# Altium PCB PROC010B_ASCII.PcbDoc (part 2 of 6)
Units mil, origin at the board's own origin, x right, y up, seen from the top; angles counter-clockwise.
Board outline 3180 x 2565 mil, 6 copper layers (TOP, L2, L3, L4, L5, BOTTOM), stack 55.54 mil thick; 362 components, 264 nets, 1248 pads, 1144 vias.
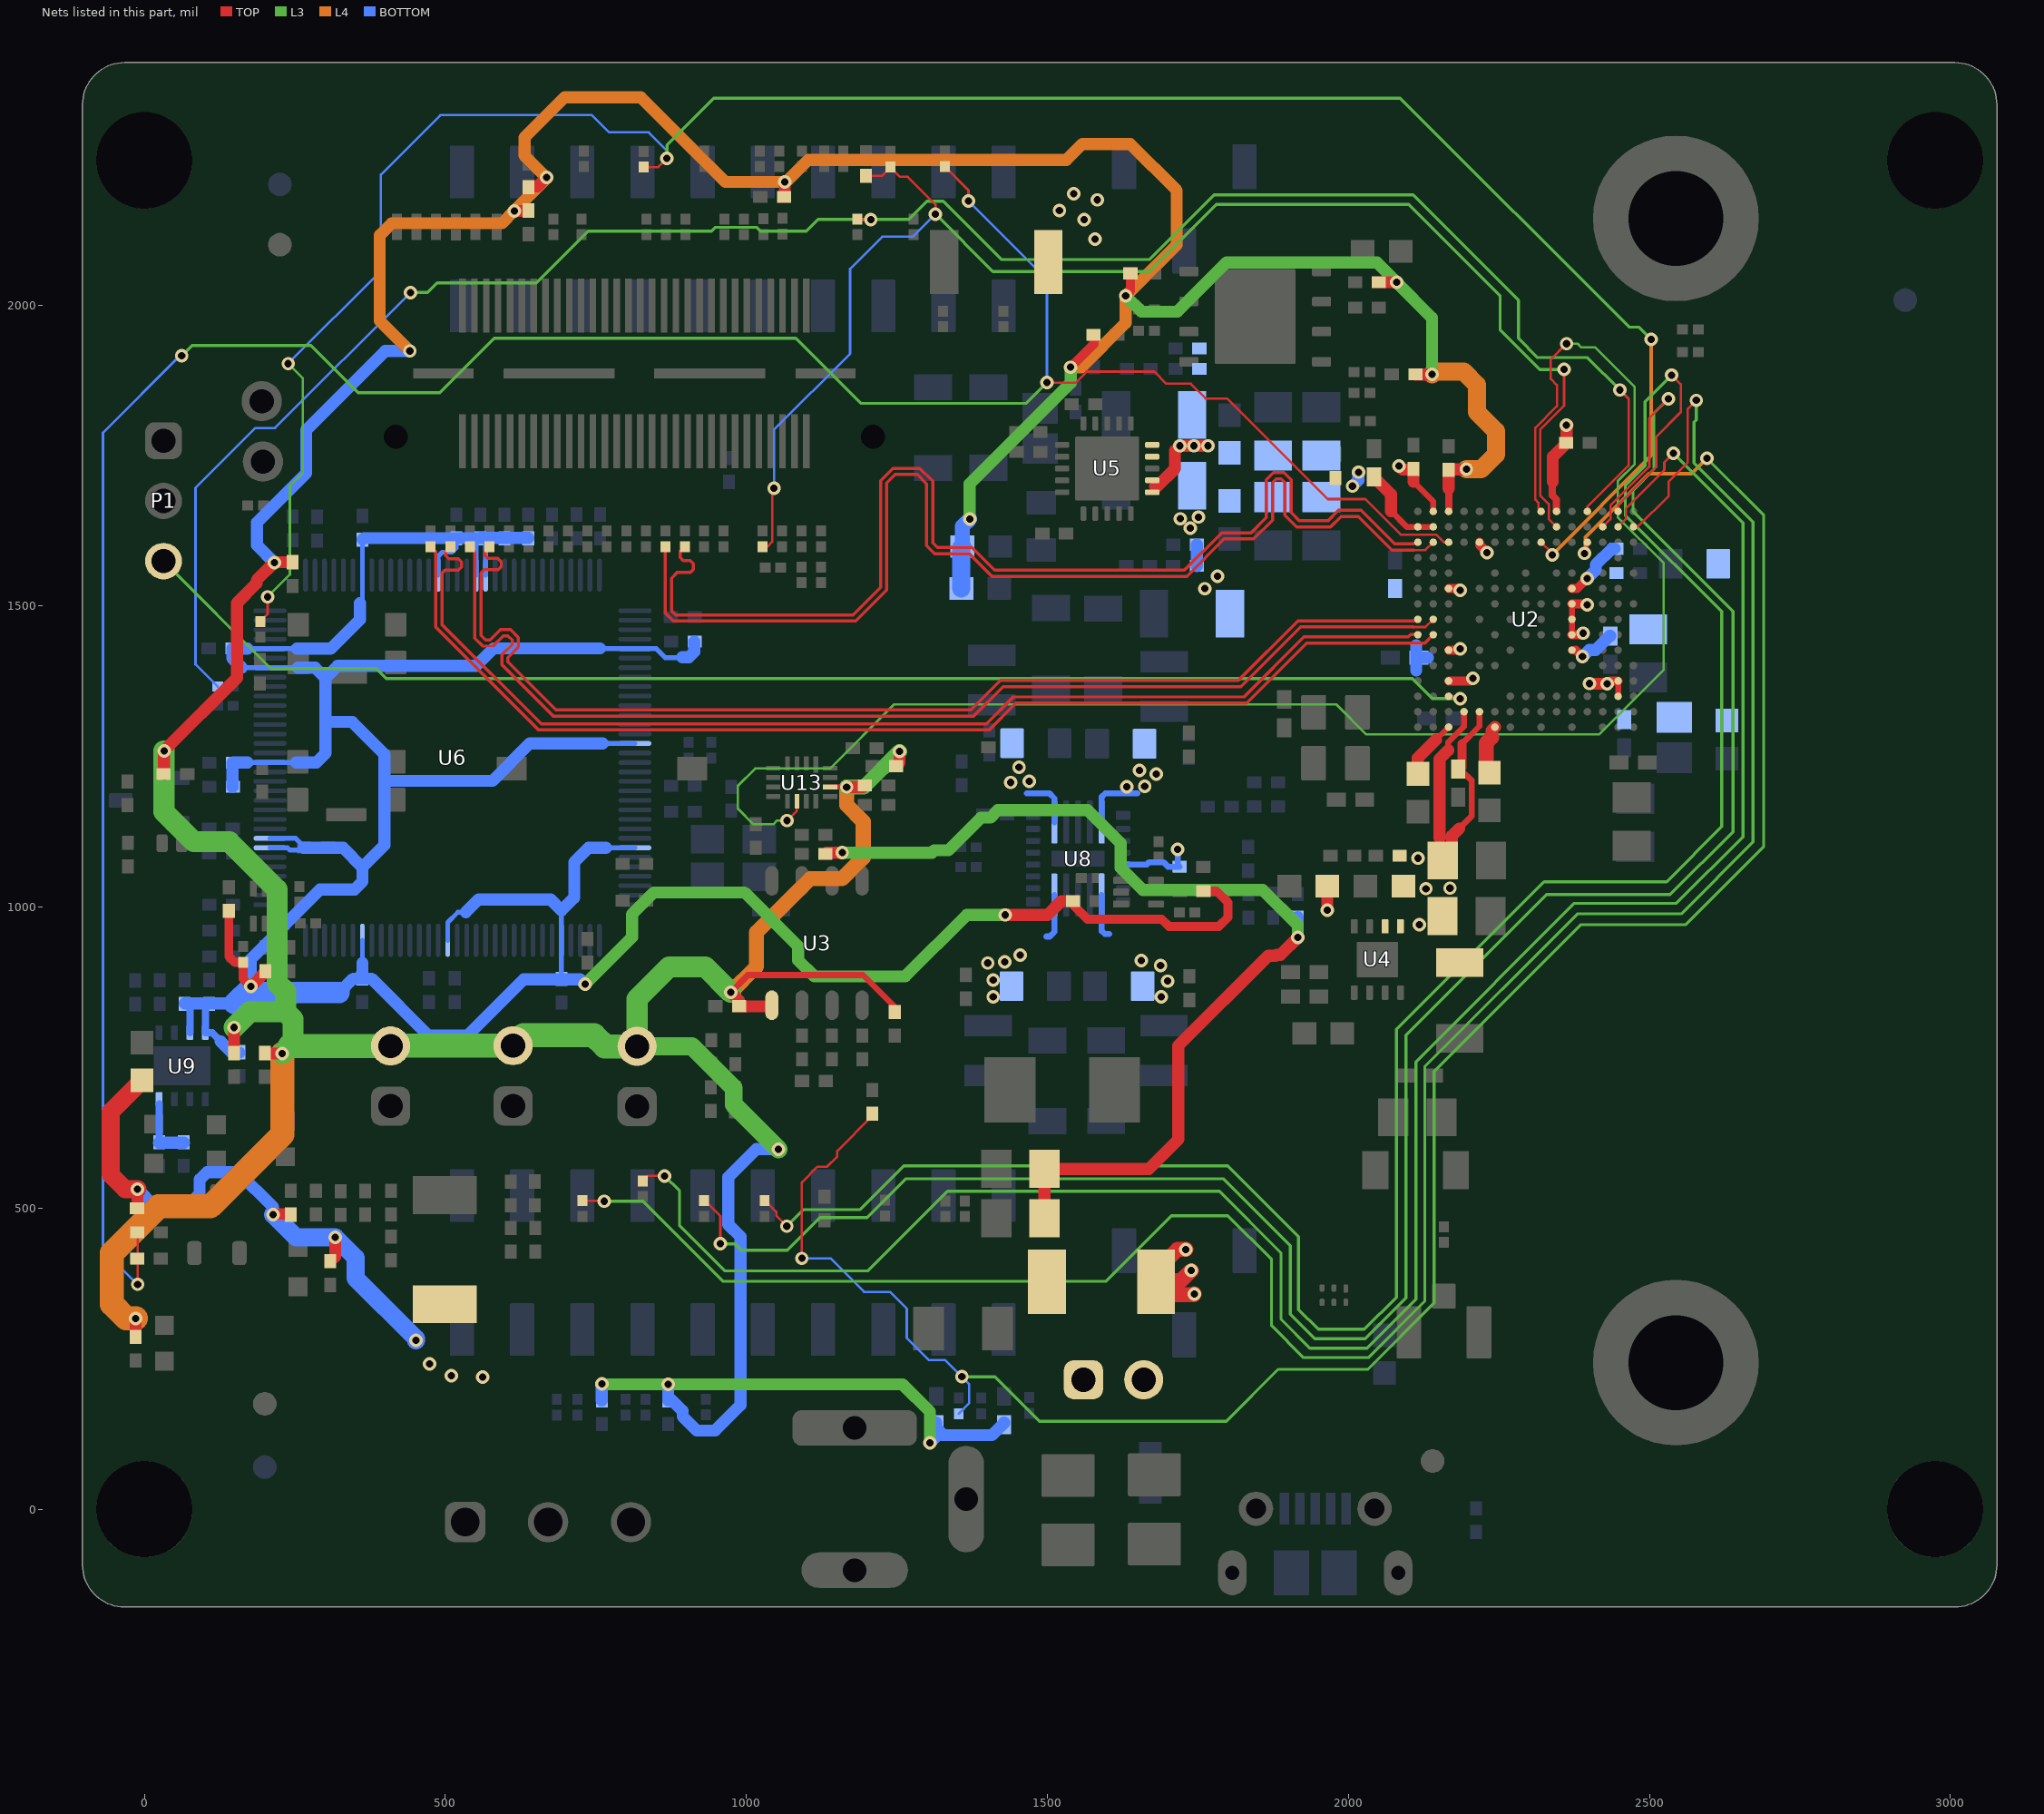
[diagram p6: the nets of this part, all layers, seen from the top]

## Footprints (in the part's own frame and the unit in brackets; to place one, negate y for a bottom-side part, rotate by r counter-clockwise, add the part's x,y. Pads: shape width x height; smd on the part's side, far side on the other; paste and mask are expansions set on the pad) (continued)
ABL0161A [mm] "BGA, 161-Balls, Body 10.4x10.4mm, Pitch 0.65mm"
  round 0.32 smd mask+0: A1(-4.55,4.55) A2(-3.9,4.55) A3(-3.25,4.55) A5(-1.95,4.55) A7(-0.65,4.55) A9(0.65,4.55) A10(1.3,4.55) A13(3.25,4.55) A14(3.9,4.55) A15(4.55,4.55) B1(-4.55,3.9) B2(-3.9,3.9) B3(-3.25,3.9) B4(-2.6,3.9) B5(-1.95,3.9) B6(-1.3,3.9) B7(-0.65,3.9) B8(0,3.9) B9(0.65,3.9) B10(1.3,3.9) B11(1.95,3.9) B12(2.6,3.9) B13(3.25,3.9) B14(3.9,3.9) B15(4.55,3.9) C1(-4.55,3.25) C2(-3.9,3.25) C3(-3.25,3.25) C4(-2.6,3.25) C5(-1.95,3.25) C6(-1.3,3.25) C7(-0.65,3.25) C8(0,3.25) C9(0.65,3.25) C13(3.25,3.25) C14(3.9,3.25) C15(4.55,3.25) D1(-4.55,2.6) D2(-3.9,2.6) D13(3.25,2.6) D15(4.55,2.6) E1(-4.55,1.95) E2(-3.9,1.95) E3(-3.25,1.95) E5(-1.95,1.95) E6(-1.3,1.95) E8(0,1.95) E10(1.3,1.95) E11(1.95,1.95) E13(3.25,1.95) E14(3.9,1.95) E15(4.55,1.95) F2(-3.9,1.3) F3(-3.25,1.3) F5(-1.95,1.3) F9(0.65,1.3) F11(1.95,1.3) F13(3.25,1.3) F14(3.9,1.3) G1(-4.55,0.65) G2(-3.9,0.65) G3(-3.25,0.65) G5(-1.95,0.65) G6(-1.3,0.65) G7(-0.65,0.65) G8(0,0.65) G10(1.3,0.65) G13(3.25,0.65) G14(3.9,0.65) G15(4.55,0.65) H2(-3.9,0) H3(-3.25,0) H5(-1.95,0) H7(-0.65,0) H9(0.65,0) H11(1.95,0) H13(3.25,0) H14(3.9,0) H15(4.55,0) J1(-4.55,-0.65) J2(-3.9,-0.65) J3(-3.25,-0.65) J5(-1.95,-0.65) J6(-1.3,-0.65) J7(-0.65,-0.65) J8(0,-0.65) J10(1.3,-0.65) J13(3.25,-0.65) J14(3.9,-0.65) J15(4.55,-0.65) K2(-3.9,-1.3) K3(-3.25,-1.3) K5(-1.95,-1.3) K7(-0.65,-1.3) K8(0,-1.3) K9(0.65,-1.3) K10(1.3,-1.3) K11(1.95,-1.3) K13(3.25,-1.3) K14(3.9,-1.3) K15(4.55,-1.3) L1(-4.55,-1.95) L2(-3.9,-1.95) L3(-3.25,-1.95) L5(-1.95,-1.95) L6(-1.3,-1.95) L8(0,-1.95) L10(1.3,-1.95) L13(3.25,-1.95) L14(3.9,-1.95) L15(4.55,-1.95) M2(-3.9,-2.6) M3(-3.25,-2.6) M13(3.25,-2.6) M14(3.9,-2.6) M15(4.55,-2.6) N1(-4.55,-3.25) N2(-3.9,-3.25) N3(-3.25,-3.25) N4(-2.6,-3.25) N5(-1.95,-3.25) N6(-1.3,-3.25) N7(-0.65,-3.25) N8(0,-3.25) N9(0.65,-3.25) N10(1.3,-3.25) N11(1.95,-3.25) N12(2.6,-3.25) N13(3.25,-3.25) N14(3.9,-3.25) N15(4.55,-3.25) P1(-4.55,-3.9) P2(-3.9,-3.9) P3(-3.25,-3.9) P4(-2.6,-3.9) P5(-1.95,-3.9) P6(-1.3,-3.9) P7(-0.65,-3.9) P8(0,-3.9) P9(0.65,-3.9) P10(1.3,-3.9) P11(1.95,-3.9) P12(2.6,-3.9) P13(3.25,-3.9) P14(3.9,-3.9) P15(4.55,-3.9) R1(-4.55,-4.55) R2(-3.9,-4.55) R3(-3.25,-4.55) R4(-2.6,-4.55) R5(-1.95,-4.55) R6(-1.3,-4.55) R7(-0.65,-4.55) R8(0,-4.55) R9(0.65,-4.55) R10(1.3,-4.55) R11(1.95,-4.55) R12(2.6,-4.55) R13(3.25,-4.55) R14(3.9,-4.55) R15(4.55,-4.55)
  silkscreen extent -5.3,-5.3 5.3,5.3
AssemblyNote [mil] "Assembly Note"
AssemblyNoteLabel [mil] "Assembly Note for PCB Labels"
CE_Mark_5mm [mil] "Minimum text height for CE Mark"
CONN_105017-0001 [mm] "Molex Micro USB-B"
  rect 0.4x1.35 smd: 1(-1.3,1.35) 2(-0.65,1.35) 3(0,1.35) 4(0.65,1.35) 5(1.3,1.35)
  oval 1.2x1.9 hole 0.6 slot 1.3 at 90 deg: 6(-3.5,-1.35) 9(3.5,-1.35)
  rect 1.5x1.9 smd: 7(-1,-1.35) 8(1,-1.35)
  round 1.45 hole 0.85: 10(2.5,1.35) 11(-2.5,1.35)
  TOP region: 3.5,-2.3 2.3,-2.3 2.3,-0.4 3.5,-0.4
  TOP region: -3.5,-0.4 -2.3,-0.4 -2.3,-2.3 -3.5,-2.3
  silkscreen extent -4.1,-0.2 4.1,1.4
CUI_PJ-002AH [mm] "DC POWER JACK, R/A, TH"
  rrect50% 1.5x5.25 hole 1 slot 3.5 at 90 deg: 1(-3,0)
  oval 1.5x4.5 hole 1 slot 3 at 90 deg: 2(3,0)
  oval 4.5x1.5 hole 1 slot 3 at 0 deg: 3(0,4.7)
  silkscreen extent -4.1,-4.5 10.7,4.5
D0008A_L [mm] "SOIC, 8-Leads, Body 4.9x3.9mm, Pitch 1.27mm, IPC High Density"
  oval 1.25x0.55 smd: 1(-2.625,1.905) 2(-2.625,0.635) 3(-2.625,-0.635) 4(-2.625,-1.905) 5(2.625,-1.905) 6(2.625,-0.635) 7(2.625,0.635) 8(2.625,1.905)
  silkscreen extent -3.1,-2.5 0.9,2.5
DBZ0003A_N [mm] "SOT23, 3-Leads, Body 2.9x1.3mm, Pitch 0.95mm, Lead Span 2.4mm, IPC Medium Density"
  rrect17% 1x0.6 smd: 1(-1.2,0.95) 2(-1.2,-0.95) 3(1.2,0)
  silkscreen extent 0.2,-1.5 0.7,1.5
DFE252012P [mm] "TOKO, Pad sizes increased as per request"
  rect 0.9x2 smd: 1(-1.05,0) 2(1.05,0)
  silkscreen extent -0.3,-1.2 0.3,1.2
DRB0008A [mm] "SON, 8-Leads, Body 3x3mm, Pitch 0.65mm, Thermal Pad 1.75x1.5mm, TI Recommended"
  rrect33% 0.6x0.3 smd: 1(-1.4,0.975) 2(-1.4,0.325) 3(-1.4,-0.325) 4(-1.4,-0.975) 5(1.4,-0.975) 6(1.4,-0.325) 7(1.4,0.325) 8(1.4,0.975)
  rrect7% 1.5x1.75 smd paste-0.75: 9(0,0)
  silkscreen extent -1.73,-1.73 1.73,1.73
DRB0008B [mm] "SON, 8-Leads, Body 3x3mm, Pitch 0.65mm, Thermal Pad 2.4x1.65mm, TI Recommended"
  rrect33% 0.6x0.3 smd: 1(-1.4,0.975) 2(-1.4,0.325) 3(-1.4,-0.325) 4(-1.4,-0.975) 5(1.4,-0.975) 6(1.4,-0.325) 7(1.4,0.325) 8(1.4,0.975)
  rrect9% 1.47x1.06 on Bottom Paste: 9(0,-0.63) 9(0,0.63)
  rrect6% 1.65x2.4 smd paste-1.2: 9(0,0)
  silkscreen extent -1.73,-1.73 1.73,1.73
DRL0006A [mm] "SOTFL, 6-Flat Leads, Body 1.2x1.6x0.6mm, Pitch 0.5mm, TI recommended"
  rrect33% 0.67x0.3 smd: 1(-0.74,0.5) 2(-0.74,0) 3(-0.74,-0.5) 4(0.74,-0.5) 5(0.74,0) 6(0.74,0.5)
  silkscreen extent -0.9,-0.95 0.5,0.95
DRY0006A [mm] "PSON, 6-Leads, Body 1x1.45mm, Pitch 0.5mm, TI Recommended"
  rrect50% 0.35x0.2 smd: 1(-0.275,0.5)
  rrect50% 0.3x0.2 smd: 2(-0.3,0) 3(-0.3,-0.5) 4(0.3,-0.5) 5(0.3,0) 6(0.3,0.5)
ESD_Overlay_Small [mil]
  silkscreen extent -62,-48 64,61
FCC_disclaimer [mil]
Fiducial10-20 [mm]
  round 1 smd mask+0: 1(0,0)
  TOP keep-out circle w1.178: c0,0 r0.5
IEC_HotSurface_Small [mil]
  silkscreen extent -107,-93 107,92
Johnson_128-0711-201 [mm] "UMC Straight Jack Receptacle, 50 Ohm, SMT"
  rrect10% 1x1.05 smd: 1(0,1.525)
  rrect10% 1.05x2.2 smd: 2(-1.475,0) 3(1.475,0)
  silkscreen extent -0.6,-1.3 0.6,-1.3
Kyocera_CX3225SA [mm] "SMD, 4-Leads, Body 3.2x2.5mm"
  rrect10% 1.05x1.45 smd: 1(-0.925,1.075) 2(-0.925,-1.075) 3(0.925,-1.075) 4(0.925,1.075)
  silkscreen extent -1.86,1.09 -1.74,1.21
Label_650x200 [mil] "Thermal Transfer Label"
  round 1 on Mech13: 0(0,0)
  silkscreen extent -325,-100 325,100
NDK_NX3225SA [mm] "NDK"
  rect 1.2x1.4 smd: 1(-0.8,1.1) 2(-0.8,-1.1) 3(0.8,-1.1) 4(0.8,1.1)
NLCV32 [mm] "TDK"
  rect 1.2x2 smd: 1(-1.6,0) 2(1.6,0)
  silkscreen extent -0.9,-1.4 0.9,1.4
On-Shore_OSTTE030161 [mm] "Terminal Block, 3.5mm, 3x1, TH"
  rrect50% 1.7x1.7 hole 1.2: 1(-3.5,0)
  round 1.7 hole 1.2: 2(0,0) 3(3.5,0)
  silkscreen extent -5.25,-3.6 5.25,4.05
PDT0128A [mm] "Thin QFP, 128-Leads, Body 14x14mm, Pitch 0.4mm"
  oval 1.4x0.2 smd: 1(-7.7,6.2) 2(-7.7,5.8) 3(-7.7,5.4) 4(-7.7,5) 5(-7.7,4.6) 6(-7.7,4.2) 7(-7.7,3.8) 8(-7.7,3.4) 9(-7.7,3) 10(-7.7,2.6) 11(-7.7,2.2) 12(-7.7,1.8) 13(-7.7,1.4) 14(-7.7,1) 15(-7.7,0.6) 16(-7.7,0.2) 17(-7.7,-0.2) 18(-7.7,-0.6) 19(-7.7,-1) 20(-7.7,-1.4) 21(-7.7,-1.8) 22(-7.7,-2.2) 23(-7.7,-2.6) 24(-7.7,-3) 25(-7.7,-3.4) 26(-7.7,-3.8) 27(-7.7,-4.2) 28(-7.7,-4.6) 29(-7.7,-5) 30(-7.7,-5.4) 31(-7.7,-5.8) 32(-7.7,-6.2) 65(7.7,-6.2) 66(7.7,-5.8) 67(7.7,-5.4) 68(7.7,-5) 69(7.7,-4.6) 70(7.7,-4.2) 71(7.7,-3.8) 72(7.7,-3.4) 73(7.7,-3) 74(7.7,-2.6) 75(7.7,-2.2) 76(7.7,-1.8) 77(7.7,-1.4) 78(7.7,-1) 79(7.7,-0.6) 80(7.7,-0.2) 81(7.7,0.2) 82(7.7,0.6) 83(7.7,1) 84(7.7,1.4) 85(7.7,1.8) 86(7.7,2.2) 87(7.7,2.6) 88(7.7,3) 89(7.7,3.4) 90(7.7,3.8) 91(7.7,4.2) 92(7.7,4.6) 93(7.7,5) 94(7.7,5.4) 95(7.7,5.8) 96(7.7,6.2)
  oval 0.2x1.4 smd: 33(-6.2,-7.7) 34(-5.8,-7.7) 35(-5.4,-7.7) 36(-5,-7.7) 37(-4.6,-7.7) 38(-4.2,-7.7) 39(-3.8,-7.7) 40(-3.4,-7.7) 41(-3,-7.7) 42(-2.6,-7.7) 43(-2.2,-7.7) 44(-1.8,-7.7) 45(-1.4,-7.7) 46(-1,-7.7) 47(-0.6,-7.7) 48(-0.2,-7.7) 49(0.2,-7.7) 50(0.6,-7.7) 51(1,-7.7) 52(1.4,-7.7) 53(1.8,-7.7) 54(2.2,-7.7) 55(2.6,-7.7) 56(3,-7.7) 57(3.4,-7.7) 58(3.8,-7.7) 59(4.2,-7.7) 60(4.6,-7.7) 61(5,-7.7) 62(5.4,-7.7) 63(5.8,-7.7) 64(6.2,-7.7) 97(6.2,7.7) 98(5.8,7.7) 99(5.4,7.7) 100(5,7.7) 101(4.6,7.7) 102(4.2,7.7) 103(3.8,7.7) 104(3.4,7.7) 105(3,7.7) 106(2.6,7.7) 107(2.2,7.7) 108(1.8,7.7) 109(1.4,7.7) 110(1,7.7) 111(0.6,7.7) 112(0.2,7.7) 113(-0.2,7.7) 114(-0.6,7.7) 115(-1,7.7) 116(-1.4,7.7) 117(-1.8,7.7) 118(-2.2,7.7) 119(-2.6,7.7) 120(-3,7.7) 121(-3.4,7.7) 122(-3.8,7.7) 123(-4.2,7.7) 124(-4.6,7.7) 125(-5,7.7) 126(-5.4,7.7) 127(-5.8,7.7) 128(-6.2,7.7)
  silkscreen extent -7.7,-6.3 6.3,6.99
RNF0026C [mm] "QFN, 26-Leads, Body 4x4.5mm, Pitch 0.5mm"
  rrect25% 0.6x0.4 smd paste-0.3: 1(-1.9,1.825) 8(-1.9,-1.825) 14(1.9,-1.825) 21(1.9,1.825)
  rrect40% 0.6x0.25 smd paste+0: 2(-1.9,1.25) 3(-1.9,0.75) 4(-1.9,0.25) 5(-1.9,-0.25) 6(-1.9,-0.75) 7(-1.9,-1.25) 15(1.9,-1.25) 16(1.9,-0.75) 17(1.9,-0.25) 18(1.9,0.25) 19(1.9,0.75) 20(1.9,1.25)
  rrect40% 0.25x1.82 smd paste-1: 9(-1,-1.54) 10(-0.5,-1.54) 11(0,-1.54) 12(0.5,-1.54) 13(1,-1.54) 22(1,1.54) 23(0.5,1.54) 24(0,1.54) 25(-0.5,1.54) 26(-1,1.54)
  rrect15% 2.24x0.66 smd paste-1: 27(0,0)
  rrect33% 0.6x0.3 on Bottom Paste: ""(-1.9,-1.775) ""(-1.9,1.775) ""(1.9,-1.775) ""(1.9,1.775)
  rrect33% 0.3x0.825 on Bottom Paste: ""(-1.575,-2.037) ""(-1.575,2.037) ""(1.575,-2.037) ""(1.575,2.037)
  rrect40% 0.25x0.81 on Bottom Paste: ""(-1,-2.045) ""(-1,-1.035) ""(-1,1.035) ""(-1,2.045) ""(-0.5,-2.045) ""(-0.5,-1.035) ""(-0.5,1.035) ""(-0.5,2.045) ""(0,-2.045) ""(0,-1.035) ""(0,1.035) ""(0,2.045) ""(0.5,-2.045) ""(0.5,-1.035) ""(0.5,1.035) ""(0.5,2.045) ""(1,-2.045) ""(1,-1.035) ""(1,1.035) ""(1,2.045)
  rrect15% 0.98x0.66 on Bottom Paste: ""(-0.59,0) ""(0.59,0)
  silkscreen extent -2.45,-2.7 2.45,2.7
RSV0016A [mm] "QFN, 16-Leads, Body 1.8x2.6mm, Pitch 0.4mm, TI Recommended"
  rect 0.7x0.2 smd: 1(-0.75,0.6)
  rect 0.6x0.2 smd: 2(-0.8,0.2) 3(-0.8,-0.2) 4(-0.8,-0.6) 9(0.8,-0.6) 10(0.8,-0.2) 11(0.8,0.2) 12(0.8,0.6)
  rect 0.2x0.6 smd: 5(-0.6,-1.2) 6(-0.2,-1.2) 7(0.2,-1.2) 8(0.6,-1.2) 13(0.6,1.2) 14(0.2,1.2) 15(-0.2,1.2) 16(-0.6,1.2)
  silkscreen extent -1.08,-1.33 1.08,1.45
RTJ0020D [mm] "QFN, 20-Leads, Body 4x4mm, Pitch 0.5mm, Thermal Pad 2.7x2.7mm, TI Recommended"
  rrect42% 0.6x0.24 smd: 1(-1.9,1) 2(-1.9,0.5) 3(-1.9,0) 4(-1.9,-0.5) 5(-1.9,-1) 11(1.9,-1) 12(1.9,-0.5) 13(1.9,0) 14(1.9,0.5) 15(1.9,1)
  rrect42% 0.24x0.6 smd: 6(-1,-1.9) 7(-0.5,-1.9) 8(0,-1.9) 9(0.5,-1.9) 10(1,-1.9) 16(1,1.9) 17(0.5,1.9) 18(0,1.9) 19(-0.5,1.9) 20(-1,1.9)
  rrect8% 1.19x1.19 on Top Paste: 21(-0.695,-0.695) 21(-0.695,0.695) 21(0.695,-0.695) 21(0.695,0.695)
  rrect4% 2.7x2.7 smd paste-1.4: 21(0,0)
  silkscreen extent -2.22,-2.22 2.23,2.23
Samtec_QSH-030-01-X-D-A [mm] "Receptacle, 0.5 mm, 30x2, TH"
  rect 2.27x0.279 smd: 1(-2.865,7.25) 2(2.865,7.25) 3(-2.865,6.75) 4(2.865,6.75) 5(-2.865,6.25) 6(2.865,6.25) 7(-2.865,5.75) 8(2.865,5.75) 9(-2.865,5.25) 10(2.865,5.25) 11(-2.865,4.75) 12(2.865,4.75) 13(-2.865,4.25) 14(2.865,4.25) 15(-2.865,3.75) 16(2.865,3.75) 17(-2.865,3.25) 18(2.865,3.25) 19(-2.865,2.75) 20(2.865,2.75) 21(-2.865,2.25) 22(2.865,2.25) 23(-2.865,1.75) 24(2.865,1.75) 25(-2.865,1.25) 26(2.865,1.25) 27(-2.865,0.75) 28(2.865,0.75) 29(-2.865,0.25) 30(2.865,0.25) 31(-2.865,-0.25) 32(2.865,-0.25) 33(-2.865,-0.75) 34(2.865,-0.75) 35(-2.865,-1.25) 36(2.865,-1.25) 37(-2.865,-1.75) 38(2.865,-1.75) 39(-2.865,-2.25) 40(2.865,-2.25) 41(-2.865,-2.75) 42(2.865,-2.75) 43(-2.865,-3.25) 44(2.865,-3.25) 45(-2.865,-3.75) 46(2.865,-3.75) 47(-2.865,-4.25) 48(2.865,-4.25) 49(-2.865,-4.75) 50(2.865,-4.75) 51(-2.865,-5.25) 52(2.865,-5.25) 53(-2.865,-5.75) 54(2.865,-5.75) 55(-2.865,-6.25) 56(2.865,-6.25) 57(-2.865,-6.75) 58(2.865,-6.75) 59(-2.865,-7.25) 60(2.865,-7.25)
  round 0 hole 1.02 unplated mask+0: MH1(2.67,10.065) MH2(2.67,-10.065)
  rect 0.43x2.54 smd: MP1(0,8.065) MP4(0,-8.065)
  rect 0.43x4.7 smd: MP2(0,3.175) MP3(0,-3.175)
  silkscreen extent -3.9,-10.66 3.62,10.66
Samtec_SSM-103-x-SV [mm] "Receptacle, 2.54mm, 3x1, SMT"
  rrect10% 1.02x1.905 smd: 1(-2.54,-1.777) 2(0,1.777) 3(2.54,-1.777)
  silkscreen extent -3.81,-2.27 3.81,1.28
Samtec_SSM-110-x-DV [mm] "Receptacle, 2.54mm, 10x2, SMT"
  rrect10% 1.02x2.22 smd: 1(-11.43,2.825) 2(-11.43,-2.825) 3(-8.89,2.825) 4(-8.89,-2.825) 5(-6.35,2.825) 6(-6.35,-2.825) 7(-3.81,2.825) 8(-3.81,-2.825) 9(-1.27,2.825) 10(-1.27,-2.825) 11(1.27,2.825) 12(1.27,-2.825) 13(3.81,2.825) 14(3.81,-2.825) 15(6.35,2.825) 16(6.35,-2.825) 17(8.89,2.825) 18(8.89,-2.825) 19(11.43,2.825) 20(11.43,-2.825)
  silkscreen extent -13.02,-2.54 12.7,2.54
Samtec_TSW-101-17-T-S [mm] "Samtec,CONN HEADER 1POS .100\" SNGL TIN"
  round 1.7 hole 1.02: 1(0,0)
  silkscreen extent -1.27,-1.27 1.27,1.27
Samtec_TSW-103-07-T-S [mm] "Header, 2.54 mm, 3x1, TH"
  rrect50% 1.55x1.55 hole 1.02: 1(-2.54,0)
  round 1.55 hole 1.02: 2(0,0) 3(2.54,0)
SMB [mil] "Molded Diode, 2-Leads, Body 5.4x3.6mm, IPC Medium Density, based on OnSemi component dimensions"
  rect 85x107.99 smd: 1(-87.01,0) 2(87.01,0)
  silkscreen extent -155,-82 125,82
SML-E1_Yellow [mm] "SMD, 2-Leads, Body 1.6x0.8mm"
  rect 0.8x0.8 smd: 1(0.825,0) 2(-0.825,0)
  silkscreen extent -1.8,-0.8 1.3,0.8
SML-LX0603SRW_SuperRed [mm] "Lumex Opto/Components Inc"
  rect 0.8x0.8 smd: 1(-0.75,0) 2(0.75,0)
  silkscreen extent 1.4,-0.53 1.78,0.53
SOD-882 [mm] "Skyworks"
  rrect42% 0.475x0.75 smd: 1(-0.412,0) 2(0.412,0)
  silkscreen extent -1.1,-0.35 -0.87,0.35
SOT-23 [mm] "SOT23, 3-Leads, Body 2.9x1.3mm, Pitch 0.95mm, Lead Span 2.5mm, IPC Medium Density"
  rrect50% 1x0.6 smd: 1(-1.2,0.95) 2(-1.2,-0.95) 3(1.2,0)
  silkscreen extent -1.62,-1.5 0.7,1.5
SW_CHS-01TB [mm] "CHS Recommended footprint"
  rect 1x1.27 smd: 1(0,3.81) 2(0,-3.81)
  silkscreen extent -1.3,-4.05 1.3,4.05
SW_KMR243GLFG [mm] "SMD, 5-Leads, Body 4.2x2.8mm"
  rrect11% 0.9x1 smd: 1(-2.05,0.8) 2(2.05,0.8) 3(-2.05,-0.8) 4(2.05,-0.8)
  rrect18% 1.7x0.55 smd: 5(0,1.425)
  silkscreen extent -3.1,0.7 -2.9,0.9
TI_Stacked_Overlay_Small [mil]
TSW-102-07-G-S [mm] "Samtec 100mil, 1x2, 230 mil above insulator"
  rrect50% 1.65x1.65 hole 1.016: 1(-1.27,0)
  round 1.65 hole 1.016: 2(1.27,0)
WEEE_Minimum [mil] "WEEElie bin"
  silkscreen extent 22,-71 54,74
WSON-8L_6x5MM_EP [mm] "SMD, 8-Leads, Body 6x5mm, Pitch 1.27mm"
  rrect25% 0.8x0.4 smd: 1(-2.8,1.905) 2(-2.8,0.635) 3(-2.8,-0.635) 4(-2.8,-1.905) 5(2.8,-1.905) 6(2.8,-0.635) 7(2.8,0.635) 8(2.8,1.905)
  rrect3% 3.4x4 smd paste-3: 9(0,0)
  rrect7% 1.468x1.698 on Top Paste: ""(-0.834,-0.949) ""(-0.834,0.949) ""(0.834,-0.949) ""(0.834,0.949)
  silkscreen extent -3.2,-2.7 3.2,2.7

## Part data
C1 C13 C14 C33 C36 C91: library part CMP-0007136-5, "CAP, CERM, 1 uF, 16 V, +/- 10%, X7R, AEC-Q200 Grade 1, 0603"
C2 C21: library part CMP-0006325-2, "CAP, CERM, 0.1 uF, 50 V, +/- 10%, X7R, AEC-Q200 Grade 1, 0402"
C3 C5 C7 C10 C12 C39 C47 C48 C51 C53 C56 C57 C68: library part CMP-0078265-1, "CAP, CERM, 0.22 µF, 16 V,+/- 10%, X7R, AEC-Q200 Grade 1, 0402"
C4 C6 C11: library part CMP-0006351-2, "CAP, CERM, 0.1 uF, 16 V, +/- 10%, X7R, 0402"
C8: library part CMP-0078219-1, "CAP, CERM, 0.1 µF, 10 V,+/- 10%, X7S, 0201"
C9 C15: library part CMP-0006367-2, "CAP, CERM, 4.7 pF, 50 V, +/- 2%, C0G/NP0, 0402"
C16 C20 C42 C43 C49 C64 C67 C71 C75 C76 C79 C84 C85 C90: library part CMP-0078241-1, "CAP, CERM, 0.1 µF, 10 V,+/- 10%, X7R, 0402"
C17 C19 C23 C32 C34 C35 C37 C38 C40 C45 C52 C58 C59 C60 C65 C72 C73 C83: library part CMP-0008017-2, "CAP, CERM, 10 uF, 10 V, +/- 10%, X7R, 0805"
C18 C22: library part CMP-0007138-4, "CAP, CERM, 0.47 uF, 16 V, +/- 10%, X7R, AEC-Q200 Grade 1, 0603"
C24: library part CMP-0078221-1, "CAP, CERM, 4700 pF, 50 V,+/- 10%, X7R, 0402"
C25 C30 C31: library part CMP-0008770-2, "CAP, CERM, 22 uF, 6.3 V, +/- 10%, X7R, AEC-Q200 Grade 1, 1206"
C26 C27: library part CMP-0078216-1, "CAP, TA, 47 µF, 10 V, +/- 10%, SMD"
C28 C29 C44 C46: library part CMP-0078224-1, "CAP, CERM, 0.01 µF, 50 V,+/- 10%, X8R, AEC-Q200 Grade 0, 0402"
C41 C61 C62: library part CMP-0078222-1, "CAP, CERM, 1 µF, 6.3 V,+/- 20%, X7S, 0402"
C50: library part CMP-0078220-1, "CAP, CERM, 0.01 µF, 25 V,+/- 10%, X7R, 0402"
C54 C55 C81 C82: library part CMP-0008811-2, "CAP, CERM, 22 uF, 10 V, +/- 10%, X7R, AEC-Q200 Grade 1, 1206"
C63 C70: library part CMP-0006494-2, "CAP, CERM, 8 pF, 50 V, +/- 6%, C0G/NP0, 0402"
C66 C69: library part CMP-0078218-1, "CAP, CERM, 0.01 µF, 16 V,+/- 10%, X7R, 0402"
C74 C77 C80: library part CMP-0006302-2, "CAP, CERM, 2.2 uF, 10 V, +/- 10%, X7S, 0402"
C78: library part CMP-0078217-1, "CAP, CERM, 15 pF, 50 V,+/- 1%, C0G/NP0, 0402"
C86 C87 C88 C89: library part CMP-0078223-1, "CAP, CERM, 390 pF, 50 V,+/- 5%, C0G/NP0, AEC-Q200 Grade 0, 0402"
"CAUTION HOT SURFACE1": library part CMP-0074837-1, "IEC 61010-1 Hot Surface Warning"
D2: library part CMP-0078187-1, "Diode, Schottky,  V, 0.01 A, SOD-882"
D3: library part CMP-0078243-1, "Diode, TVS, Uni, 5.8 V, 10.5 Vc, AEC-Q101, SMB"
DS1 DS2 DS5: library part CMP-0002876-1, "LED, Super Red, SMD"
DS3 DS4: library part CMP-0002977-2, "LED, Yellow, SMD"
"ESD Susceptible1": library part CMP-0074840-1, "ESD Susceptible Symbol"
F1: library part CMP-0003458-2, "Fuse, 5 A, 32VAC/VDC, SMD"
FB1 FB2: library part CMP-0003364-1, "Ferrite Bead, 30 ohm @ 100 MHz, 4 A, 0805"
FID1 FID2 FID3 FID4 FID5 FID6 FID7: library part CMP-0077181-1, "Fiducial mark.  There is nothing to buy or mount."
J1: library part CMP-0075524-1, "Receptacle, 0.5 mm, 30x2, Gold, TH"
J2: library part CMP-0055788-1, "UMC Straight Jack Receptacle, 50 Ohm, Gold, SMT"
J3: library part CMP-0075352-1, "Terminal Block, 3.5mm, 3x1, Tin, R/A, TH"
J4 J7: library part CMP-0078183-1, "Receptacle, 2.54mm, 3x1, Gold with Tin tail, SMT"
J5 J6: library part CMP-0078182-1, "Receptacle, 2.54mm, 10x2, Gold with Tin tail, SMT"
J8: library part CMP-0055293-1, "Connector, Receptacle, Micro-USB Type B, R/A, Bottom Mount SMT"
L1 L2 L3 L4: library part CMP-0058946-1, "Inductor, Shielded, 470 nH, 4.7 A, 0.021 ohm, SMD"
L5 L7 L8 L9: library part CMP-0083745-1, "Inductor, Wirewound, Ferrite, 100 nH, 2.85 A, 0.024 ohm, AEC-Q200 Grade 1, SMD"
LBL1: library part CMP-0003625-1, "Thermal Transfer Printable Labels, 0.650\" W x 0.200\" H - 10,000 per roll"
Logo1: library part CMP-0074838-1, "Texas Instrument Corporate Signature"
Logo2: library part CMP-0074847-1, "FCC_disclaimer"
Logo3: library part CMP-0074769-1
LOGO4: library part CMP-0074844-1
P1: library part CMP-0075530-2, "Header, 2.54 mm, 3x1, Tin, TH"
P2 P3 P4 P5: library part CMP-0075405-2, "Header, 100mil, 2x1, Gold, TH"
P6: library part CMP-0078270-1, "DC POWER JACK, R/A, TH"
Q1 Q2: library part CMP-0000947-2, "MOSFET, N-CH, 100 V, 0.17 A, SOT-23"
R1 R2 R3 R4 R5 R6 R7 R8 R9 R10 R17 R18 R19 R20 R21 R22 R23 R24 R25 R26 R27 R28 R29 R30 R31 R32 R33 R35 R36 R48 R49 R50 R51 R52 R53 R54 R55 R56 R57 R58 R59 R60 R61 R62 R63 R64 R65 R66 R67 R69 R70 R71 R72 R75 R76 R94 R102 R104 R105 R106 R108 R109 R111 R135 R136 R144 R146 R162 R163 R164 R165 R166 R167 R168 R169 R180 R181 R182 R185 R186 R188 R197 R198: library part CMP-0027008-4, "RES, 0, 5%, 0.05 W, 0201"
R11 R12 R37 R78 R97 R107 R119 R120 R128 R129 R141 R152 R159 R177 R183 R187: library part CMP-0026992-2, "RES, 0, 5%, 0.063 W, 0402"
R13 R14 R15 R16 R41 R43 R46 R47 R73 R74 R81 R83 R84 R86 R89 R91 R98 R113 R145 R148 R155 R178 R179 R184 R196: library part CMP-0025958-3, "RES, 10.0 k, 1%, 0.063 W, AEC-Q200 Grade 0, 0402"
R34 R115 R118: library part CMP-0016044-3, "RES, 0, 5%, 0.75 W, AEC-Q200 Grade 0, 2010"
R38: library part CMP-0026395-2, "RES, 47.5 k, 1%, 0.063 W, AEC-Q200 Grade 0, 0402"
R39 R40 R42 R44 R45: library part CMP-0027275-3, "RES, 33.2, 1%, 0.05 W, 0201"
R68 R77 R79 R80 R154: library part CMP-0026993-2, "RES, 100, 5%, 0.1 W, AEC-Q200 Grade 0, 0402"
R82: library part CMP-0025993-3, "RES, 12.7 k, 1%, 0.063 W, AEC-Q200 Grade 0, 0402"
R85 R87: library part CMP-0026491-2, "RES, 61.9, 1%, 0.063 W, AEC-Q200 Grade 0, 0402"
R88 R96 R114: library part CMP-0026574-2, "RES, 82.5 k, 1%, 0.063 W, AEC-Q200 Grade 0, 0402"
R90 R189: library part CMP-0078194-1, "RES, 360, 5%, 0.1 W, AEC-Q200 Grade 0, 0402"
R92 R95 R99: library part CMP-0026557-2, "RES, 7.87 k, 1%, 0.063 W, AEC-Q200 Grade 0, 0402"
R93 R101 R112: library part CMP-0026542-2, "RES, 750, 1%, 0.063 W, AEC-Q200 Grade 0, 0402"
R100 R103 R116 R117 R160: library part CMP-0078212-1, "RES, 510, 5%, 0.1 W, AEC-Q200 Grade 0, 0402"
R110 R138 R158 R172 R173: library part CMP-0025950-3, "RES, 100 k, 1%, 0.063 W, AEC-Q200 Grade 0, 0402"
R121 R132: library part CMP-0078211-2, "RES, 3.00 k, 1%, 0.063 W, AEC-Q200 Grade 0, 0402"
R122 R131 R139: library part CMP-0026099-2, "RES, 1.96 k, 1%, 0.063 W, AEC-Q200 Grade 0, 0402"
R123 R124 R126 R127 R140: library part CMP-0026071-3, "RES, 1.00 k, 1%, 0.063 W, AEC-Q200 Grade 0, 0402"
R125 R195: library part CMP-0025958-2, "RES, 10.0 k, 1%, 0.063 W, 0402"
R130 R133 R137 R161 R175 R176: library part CMP-0025884-3, "RES, 0, 5%, 0.125 W, 0603"
R134: library part CMP-0026404-2, "RES, 49.9, 1%, 0.063 W, AEC-Q200 Grade 0, 0402"
R142 R150: library part CMP-0026701-1, "RES, 4.99 k, 1%, 0.1 W, AEC-Q200 Grade 0, 0402"
R143 R147: library part CMP-0026414-2, "RES, 4.99 k, 1%, 0.063 W, AEC-Q200 Grade 0, 0402"
R149: library part CMP-0078193-1, "RES, 1.0 k, 5%, 0.1 W, AEC-Q200 Grade 0, 0402"
R151 R153: library part CMP-0078210-2, "RES, 330 k, 1%, 0.063 W, AEC-Q200 Grade 0, 0402"
R156: library part CMP-0026403-2, "RES, 49.9 k, 1%, 0.063 W, AEC-Q200 Grade 0, 0402"
R157 R174: library part CMP-0078244-2, "RES, 30.0 k, 1%, 0.063 W, AEC-Q200 Grade 0, 0402"
R170 R171: library part CMP-0026244-2, "RES, 2.94 k, 1%, 0.063 W, AEC-Q200 Grade 0, 0402"
R190 R191 R192 R193: library part CMP-0026363-2, "RES, 3.83, 1%, 0.063 W, AEC-Q200 Grade 0, 0402"
R194: library part CMP-0026413-2, "RES, 4.87 k, 1%, 0.063 W, AEC-Q200 Grade 0, 0402"
S1: library part CMP-0002163-2, "Switch, Slide, SPST, Top Slide, SMT"
SW1 SW2: library part CMP-0002325-1, "Switch, SPST-NO, Off-Mom, 0.01 A, 32 VDC, SMD"
TP1 TP2: library part CMP-0055993-1, "Header, 100mil, 1x1, Tin, TH"
U1: library part CMP-0079267-1, "2.3V-3.6V, 16M-BIT [x 1/x 2/x 4] CMOS FLASH Memory, WSON-8"
U2: library part CMP-0081285-1, "Single Chip 77 and 79 GHz FMCW Transceiver, ABL0161A (FCBGA-161)"
U3: library part CMP-0075992-1, "Automotive Fault Protected CAN Transceiver With Flexible Data-Rate, D0008A (SOIC-8)"
U4: library part CMP-0073870-2, "Automotive Low-Noise, Wide-Bandwidth, High PSRR, Low-Dropout 1-A Linear Regulator, DRB0008A (VSON-8)"
U5: library part CMP-0073732-2, "Dual, 1-A, Low Noise (3.8-uVRMS), LDO Voltage Regulator, RTJ0020D (WQFN-20)"
U6: library part CMP-0029856-2, "Tiva C Series Microcontroller, 1024 KB Flash, 256 KB SRAM, 12 Bit, 20 Channels, -40 to 105 degC, 128-Pin TQFP (PDT), Green (RoHS & no Sb/Br), Tray"
U7: library part CMP-0033001-1, "Precision Micropower Shunt Voltage Reference, 0.5% accuracy, 2.5 V, 15 ppm / degC, 15 mA, -40 to 125 degC, 3-pin SOT-23 (DBZ), Green (RoHS & no Sb/Br)"
U8: library part CMP-0079120-1, "4-A + 2.5-A + Two 1.5-A Buck Converters With Integrated Switches, RNF0026C (VQFN-HR-26)"
U9: library part CMP-0036402-3, "Single Output High PSRR LDO, 1 A, Adjustable 1.2 to 5.5 V Output, 2.7 to 5.5 V Input, 8-pin SON (DRB), -40 to 125 degC, Green (RoHS & no Sb/Br)"
U10: library part CMP-0043115-2, "ESD-Protection Array for High-Speed Data Interfaces, 4 Channels, -40 to +85 degC, 6-pin SON (DRY), Green (RoHS & no Sb/Br)"
U11 U12: library part CMP-0067397-2, "1.4V-Capable +/-0.5degC Temperature Sensor with Alert Function and I2C/SMBus interface in SOT-563, DRL0006A (SOT-OTHER-6)"
U13: library part CMP-0067415-1, "10-Ohm Quad SPDT Analog Switch, RSV0016A (UQFN-16)"
Y1: library part CMP-0004694-3, "Crystal, 40 MHz, 8pF, SMD"
Y2: library part CMP-0078214-2, "Crystal, 16 MHz, 15 ppm, 8 pF, AEC-Q200 Grade 1, SMD"
ZZ1: library part CMP-0003616-3
ZZ2: library part CMP-0077236-1
ZZ3: library part CMP-0077237-1
ZZ4: library part CMP-0077238-1
ZZ5: library part CMP-0077238-1, "Micro USB cable, Brackets, Screws, Nuts, Jumpers and Bump on need to be placed in a platic bag"

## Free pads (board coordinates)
  round 275.59 hole 157.48: 0(2543.95,2143.55) 1(2543.95,243.55)
  round 160 hole 160 unplated: ""(0,0) ""(0,2240) ""(2974.5,0) ""(2974.5,2240)

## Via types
v1: diameter 22.4, hole 12.2, TOP to BOTTOM, tented both sides, 621 vias
v2: diameter 15.74, hole 5.9, TOP to L2, tented top, 508 vias
v3: diameter 19.68, hole 7.87, TOP to BOTTOM, tented top, 7 vias
v4: diameter 19.68, hole 7.87, TOP to BOTTOM, 4 vias
v5: diameter 19.68, hole 7.87, TOP to BOTTOM, tented both sides, 3 vias
v6: diameter 19.68, hole 7.87, TOP to BOTTOM, tented bottom, 1 vias

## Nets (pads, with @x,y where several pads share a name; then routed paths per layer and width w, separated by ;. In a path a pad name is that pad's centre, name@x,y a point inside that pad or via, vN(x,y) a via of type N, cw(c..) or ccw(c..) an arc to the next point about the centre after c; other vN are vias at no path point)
3V3_BRD: C41.2 C42.2 C43.2 C50.2 C61.2 C76.2 C77.2 C78.2 R124.2 R127.2 R134.2 R140.2 R155.2 R156.2 R179.2 R183.2 R184.2 R187.2 R188.1 U6.7 U6.8 U6.16 U6.26 U6.28 U6.39 U6.47 U6.51 U6.52 U6.69 U6.79 U6.90 U6.101 U6.113 U6.122 U9.3 U9.4 | length 6461.6
  TOP w15: R184.2@140.38,994.45 R184.2@140.38,993.66 140.38,918.01 150.16,908.23 R188.1@163.83,908.23 163.83,881.17 v1(177,868) ; R179.2@1543.45,1009.92 1543.45,1003.19 1566.64,980 1690,980 1702,968 1784.72,968 1799.73,983.01 1799.73,1007.95 1781,1026.68 R183.2@1759.34,1026.68 R183.2@1758.55,1026.68
  TOP w20: v1(177,868) 200.98,891.98 R187.2@200.98,893.66 ; v1(1430,987) 1500.36,987 1523.28,1009.92 R179.2@1542.66,1009.92 R179.2@1543.45,1009.92
  L3 w20: v1(732,872) 810.21,950.21 810.21,988.21 846.3,1024.3 996.79,1024.3 1086.18,934.9 1086.18,911.5 1112.78,884.9 1263.9,884.9 1366,987 v1(1430,987)
  BOTTOM w8: 161.85,1397.65 254.85,1397.65 ; 171.33,1240.17 252.33,1240.17 ; 171.36,1429.14 253.36,1429.14 ; U6.7@208.64,1098.43 238.07,1098.43 242,1094.5 260.32,1094.5 264.25,1098.43 264.25,1101.25 251.32,1114.18 U6.8@208.64,1114.18 ; 362.18,907.32 U6.122@362.18,944.89 ; 362.18,1508.68 C43.2@362.18,1610.21 ; U6.47@488.17,1551.19 488.17,1582.5 495.15,1589.48 511.07,1589.48 518.22,1596.62 C42.2@518.22,1612.16 ; U6.113@503.92,944.89 503.92,974.56 520.86,991.5 534,991.5 ; C42.2@518.03,1612.36 C42.2@518.22,1612.55 ; U6.51@551.16,1551.19 551.16,1605.41 558.3,1612.55 566.91,1603.94 U6.52@566.91,1551.19 ; R155.2@692.89,880.16 692.89,994.61 ; 757,1429.5 757.36,1429.14 850.37,1429.14 865.11,1414.4 892.75,1414.4 ; 761.16,1271.66 U6.79@814.94,1271.66 ; 767,1098.5 814.87,1098.5 U6.90@814.94,1098.43
  BOTTOM w8.4: 358,1504.5 362.18,1508.68 ; C43.2@362.18,1610.21 C43.2@362.52,1610.55 ; R155.2@692.78,880.05 R155.2@692.89,880.16 ; 892.75,1414.4 893.34,1414.99
  BOTTOM w12: C78.2@67.1,839.85 75.63,831.32 U9.3@75.63,791.44 ; C77.2@108.82,839.85 101.22,832.25 U9.4@101.22,791.44 112.56,791.44 127,777
  BOTTOM w20: C78.2@67.1,839.85 108.82,839.85 148.85,839.85 ; 127,777 145.91,758.09 R156.2@158.03,758.09 ; R140.2@146.55,1199.52 146.55,1239.66 147.06,1240.17 171.33,1240.17 ; 161.85,1397.65 145.95,1413.55 145.95,1429.4 146.21,1429.14 171.36,1429.14 ; v1(177,868) 177,914 292,1029 349,1029 362.18,1042.18 362.18,1066.32 ; 252.33,1240.17 285.67,1240.17 301,1255.5 301,1307.5 ; 253.36,1429.14 309.64,1429.14 358,1477.5 358,1504.5 ; 254.85,1397.65 283.85,1397.65 301,1380.5 ; 264.25,1098.43 330.07,1098.43 362.18,1066.32 ; 324.01,858 347.16,881.15 C76.2@361.92,881.15 ; 362.18,907.32 362.18,881.41 C76.2@361.92,881.15 ; C43.2@362.52,1610.55 364.52,1612.55 518.22,1612.55 558.3,1612.55 558.7,1612.95 R124.2@637.72,1612.95 ; 534,991.5 555,1012.5 675,1012.5 692.89,994.61 714,1015.72 714,1074.5 738,1098.5 767,1098.5 ; v1(732,872) 723.95,880.05 692.78,880.05 630.21,880.05 536.46,786.3 472.2,786.3 377.35,881.15 C76.2@361.92,881.15 ; 757,1429.5 580,1429.5 551,1400.5 321,1400.5 301,1380.5 ; 761.16,1271.66 640.16,1271.66 578,1209.5 399,1209.5 ; 893.34,1414.99 904.49,1414.99 913.55,1424.05 R134.2@913.55,1440.6 ; 301,1307.5 345.46,1307.5 399,1253.96 399,1209.5 ; 301,1307.5 301,1380.5 ; 362.18,1066.32 399,1103.14 399,1209.5
  BOTTOM w35: 148.85,839.85 v1(177,868) 187,858 324.01,858
3V3_MON_XDS_1: R158.2 R159.2 U9.8 | length 106
  BOTTOM w12: R159.2@24.43,608.61 U9.8@24.43,673.31
  BOTTOM w20: R159.2@24.43,608.61 65.54,608.61 R158.2@65.68,608.75
5V_IN: FB1.2 FB2.2 P5.1 R34.2 R78.2 R100.2 R103.2 R115.2 R117.2 R118.1 R149.2 R176.2 | length 2718.1
  TOP w20: R103.2@-11.33,500.07 v1(-11.33,531.5) ; v1(214,489.5) 216,489.5 216,490.16 R100.2@242.91,490.16 ; R117.2@308.61,411.05 317,419.44 v1(317,451.5) ; R78.2@1131.38,1088.29 1133.38,1090.29 v1(1159.19,1090.29) ; FB1.2@1495.18,483.01 FB2.2@1495.18,565.13 1668.47,565.13 1717.57,614.23 1717.57,769.57 1867,919 1879.11,919 1880.94,920.83 1887.33,920.83 v1(1916,949.5)
  TOP w30: v1(-11.33,531.5) -32,531.5 -56,555.5 -56,660 R176.2@-4,712
  L3 w20: v1(1159.19,1090.29) 1308.15,1090.29 1312.05,1094.19 1335.41,1094.19 1389.7,1148.47 1405.4,1148.47 1417.73,1160.8 1566.87,1160.8 1621.82,1105.85 1621.82,1065.13 1658.74,1028.2 1857.86,1028.2 1916,970.06 v1(1916,949.5)
  BOTTOM w20: v1(-11.33,531.5) 16.73,503.5 71.25,503.5 91.81,524.06 91.81,547.66 104.05,559.9 155.6,559.9 214,501.5 v1(214,489.5) ; v1(1916,949.5) 1916.14,949.64 R149.2@1916.14,982.46 R149.2@1916.14,983.25
  BOTTOM w30: v1(214,489.5) 252,451.5 v1(317,451.5) 351,417.5 351,383.5 451,283.5 v1(451,280.5)
  other v1: 562,219.5 510,221.5 474,241.5 1579,2109.5 1561,2141.5 1520,2156.5 1583,2174.5 1544,2184.5
5V_UNREG: C59.2 C60.2 C68.2 C72.2 C73.2 P5.2 R118.2 U8.9 U8.13 U8.18 U8.22 U8.26 | length 679.7
  TOP w25: v1(1730,431.5) 1716,431.5 1686.01,401.51 R118.2@1686.01,379.75 ; v1(1739,396.5) 1722.25,379.75 R118.2@1686.01,379.75 ; v1(1744,357.5) 1743,356.5 1709.26,356.5 R118.2@1686.01,379.75
  BOTTOM w10: 1465.59,1189.06 1503.26,1189.06 1511.63,1180.69 U8.9@1511.63,1141.13 ; 1498.57,951.17 1503.9,951.17 1511.63,958.9 U8.26@1511.63,1019.87 ; U8.22@1590.37,1019.87 1590.37,960.27 1595.3,955.34 1603.08,955.34 ; U8.13@1590.37,1141.13 1590.37,1183.19 1596.05,1188.86 1649.74,1188.86 ; U8.18@1625.81,1070.65 1665.16,1070.66 1669,1074.5 1692.82,1074.5 1700.32,1067 C68.2@1719.76,1067 1716.42,1070.34 v1(1716.42,1096.08)
  other v1: 1410,851 1689,851 1700,877 1410,879 1688,903 1401,907 1429,909 1656,911 1455,920 1631.87,1199.66 1661.71,1200.36 1439,1207 1470,1209 1680.9,1220.81 1652.89,1226.69 1453,1232
+3.3VD: C5.1 C20.2 C90.2 P2.2 P3.2 P4.2 R14.2 R15.2 R16.2 R37.1 R38.2 R41.2 R43.2 R68.2 R74.2 R90.2 R91.2 R125.2 R130.2 R133.2 R170.2 R171.2 R172.2 R173.2 R178.1 R189.2 U2.R13 U3.5 U13.14 | length 10127.1
  TOP w7.87: U13.14@1139.1,1199.34 v1(1166.57,1199.34)
  TOP w10: v1(974,858.48) 1002.52,887 1193.73,887 1246.5,834.23 R178.1@1246.5,825.86
  TOP w12: 2166.55,1694.7 2166.6,1694.65 U2.R13@2166.6,1657.03
  TOP w15: v1(1538.68,1896.5) 1577.39,1935.21 R43.2@1577.39,1950.4 ; v1(1630,2015) 1638,2023 R38.2@1638,2052.34
  TOP w19.68: R189.2@-14.4,286.41 v1(-14.4,316.79)
  TOP w20: R74.2@32.75,1221.14 v1(32.75,1259.5) 153.9,1380.65 153.9,1504.98 186.63,1537.71 186.63,1542.68 v1(216,1572.05) 216.79,1572.84 R68.2@246.04,1572.84 ; R91.2@149,757.57 v1(149,800) ; R90.2@200.46,756.69 v1(229,756.69) ; v1(614.45,2156.05) R16.2@638.2,2156.05 ; R14.2@638.26,2196.95 653.45,2196.95 v1(668,2211.5) ; v1(974,858.48) 987.19,845.29 987.19,835.45 987.39,835.25 U3.5@1042.01,835.25 ; R15.2@1062.49,2179.56 1063.86,2180.92 v1(1063.86,2204.17) ; v1(1166.57,1199.34) 1193.95,1199.34 C90.2@1196.58,1201.97 ; R125.2@1248.95,1234.12 1254.47,1239.64 v1(1254.47,1258.49) ; R37.1@2050.61,2037.7 v1(2080,2037.7) ; R41.2@2111.34,1884.48 v1(2139,1884.48) ; 2166.55,1694.7 C5.1@2166.55,1726.1 2167.47,1727.02 v1(2196,1727.02)
  L3 w20: v1(759.88,208.38) 760.94,207.32 v1(870.18,207.32) 1259.68,207.32 1305,162 v1(1305,110.5) ; v1(1371,1644.5) 1371,1702.77 1538.68,1870.45 v1(1538.68,1896.5) ; v1(1630,2015) 1656.19,1988.81 1716.01,1988.81 1797.54,2070.34 2047.36,2070.34 v1(2080,2037.7) 2139,1978.7 v1(2139,1884.48)
  L3 w25: v1(1166.57,1199.34) 1195.31,1199.34 v1(1254.47,1258.49)
  L3 w30: P4.2@818.44,768.75 909.56,768.75 979,699.31 979,672 v1(1053,598)
  L3 w35: v1(32.75,1259.5) 32.75,1158.15 82.4,1108.5 140.99,1108.5 220.51,1028.98 220.51,874.14 234.9,859.75 234.9,826 ; v1(149,800) 175,826 234.9,826 ; v1(229,756.69) 241.73,769.42 246.99,774.68 246.99,813.91 234.9,826 ; P4.2@818.44,768.75 818.44,847.23 872.04,900.83 931.65,900.83 v1(974,858.48)
  L3 w40: 241.73,769.42 P3.2@409,769.42 409.33,769.75 P2.2@612.44,769.75 629.74,787.05 746.82,787.05 765.12,768.75 P4.2@818.44,768.75
  L4 w20: v1(441,1923.5) 391,1973.5 391,2115.5 411,2135.5 593.9,2135.5 v1(614.45,2156.05) 668,2209.6 v1(668,2211.5) 631.64,2247.86 631.64,2278.23 698.3,2344.88 824.86,2344.88 965.58,2204.17 v1(1063.86,2204.17) 1065.85,2204.17 1102.43,2240.75 1531.64,2240.75 1558.05,2267.16 1637.7,2267.16 1714.91,2189.95 1714.91,2099.91 v1(1630,2015) 1630,1969.94 1556.55,1896.5 v1(1538.68,1896.5)
  L4 w25: v1(974,858.48) 1016.63,901.11 1016.63,958.14 1105.59,1047.11 1159,1047.11 1194.19,1082.3 1194.19,1141.98 1166.57,1169.6 v1(1166.57,1199.34)
  L4 w30: v1(2139,1884.48) 2143.47,1888.95 2192,1888.95 2213.38,1867.57 2213.38,1822.12 2245,1790.5 2245,1751.55 2220.47,1727.02 v1(2196,1727.02)
  L4 w40: v1(-14.4,316.79) -29.94,316.79 -53.75,340.6 -53.75,425.27 23.85,502.87 109.8,502.87 229,622.07 v1(229,756.69)
  BOTTOM w20: v1(216,1572.05) 187.14,1600.91 187.14,1638.64 269,1720.5 269,1792.51 399.99,1923.5 v1(441,1923.5) ; R173.2@759.88,180.84 v1(759.88,208.38) ; v1(870.18,207.32) R172.2@870.18,180.84 876.51,180.84 894.11,163.23 894.11,154 917.44,130.67 948.06,130.67 990.2,172.81 990.2,452.62 970.15,472.67 970.15,551.45 1016.7,598 v1(1053,598) ; v1(1305,110.5) 1317.5,123 1328,123 ; R171.2@1315.37,144.16 R171.2@1315.37,140.23 1315.37,135.63 1328,123 ; R170.2@1428.02,144.16 1428.02,143 1408.02,123 1328,123
  BOTTOM w25: R130.2@1358.81,1598.71 1358.81,1632.31 v1(1371,1644.5)
  BOTTOM w30: R133.2@1357.19,1529.05 1357.19,1597.09 R130.2@1358.81,1598.71
AR_1P3_RF1: C36.2 C37.2 C38.2 C45.1 C46.2 C47.1 L5.2 R131.2 U2.G5 U2.H5 U2.J5 U5.14 U5.15 | length 132.3
  TOP w10: U2.G5@2371.32,1452.31 U2.J5@2371.32,1503.49
  TOP w15: U2.G5@2371.32,1452.31 2387.56,1452.31 v1(2390.05,1454.8) ; U2.J5@2371.32,1503.49 2394.83,1503.49 v1(2396.62,1501.7)
  BOTTOM w20: C46.2@1748.19,1566.52 1748.43,1566.76 R131.2@1748.43,1601.78
  other v1: 1737.33,1629.38 1720.71,1644.84 1751.15,1647.68
AR_1P3_RF2: C28.2 C33.2 C34.2 C35.2 C57.1 C58.1 L8.2 R122.2 R137.1 U2.C2 U2.D2 U5.11 U5.12 | length 208.2
  TOP w10: U2.C2@2448.09,1349.95 U2.D2@2448.09,1375.54
  TOP w15: v1(2430.15,1371) 2434.69,1375.54 U2.D2@2448.09,1375.54
  TOP w20: 1678.94,1698.93 1682.8,1698.93 1711.9,1728.03 1711.9,1757.66 v1(1720.3,1766.07) v1(1743.7,1766.07) v1(1766.84,1766.07) ; v1(2400.5,1371.2) 2400.7,1371 v1(2430.15,1371)
AR_1V2: C3.1 C4.1 C6.1 C7.1 L9.2 U2.F13 U2.N11 U2.P14 U2.P15 U2.R6 U2.R14 | length 492.5
  TOP w10: 2071,1657.5 2097.06,1631.44 U2.P14@2141.01,1631.44 ; 2108,1706.54 2141.01,1673.53 U2.R14@2141.01,1657.03
  TOP w12: 2339.55,1706.05 2339,1705.5 2339,1683.5 2345.73,1676.77 U2.R6@2345.73,1657.03
  TOP w15: U2.F13@2166.6,1426.72 2183.67,1426.72 v1(2185.75,1428.8) ; U2.N11@2217.78,1605.85 2217.78,1601.72 2229.95,1589.55 v1(2229.95,1588.6)
  TOP w20: C6.1@2042.55,1718.5 C6.1@2042.55,1714.18 2071,1685.73 2071,1657.5 ; v1(2084,1732.5) 2090.22,1726.48 2105.35,1726.73 C4.1@2108,1727.74 2108,1706.54 ; 2339.55,1706.05 2339.55,1748.1 2362.25,1770.8 v1@2362.25,1800.5 ; v1(2362,1800.5) v1@2362.25,1800.5 ; v1@2364.31,1800.5 v1@2362.25,1800.5
  BOTTOM w20: v1(2006.84,1698.99) 2016.75,1708.9 v1(2016.75,1722.26)
  other v1: 1761.62,1528.79 1782.43,1549.59
AR_1V4_APLL: C13.1 U2.A10 | length 83.7
  TOP w20: 2238,1281.5 2238,1293.4 U2.A10@2243.37,1298.77
  TOP w25: C13.1@2234.45,1223.4 2228.91,1228.94 2228.91,1272.41 2238,1281.5
AR_1V4_SYNTH: C14.1 U2.A13 | length 98.7
  TOP w10: 2145.55,1277.72 U2.A13@2166.6,1298.77
  TOP w20: C14.1@2115.45,1221.3 2115.45,1247.62 2145.55,1277.72
AR_1V8: C12.1 C17.1 C18.1 C19.1 C39.1 C48.1 C51.1 C52.1 C53.1 C91.2 L7.2 R82.2 U2.B11 U2.B12 U2.D13 U2.F5 U2.K5 U2.K13 U4.1 U4.2 | length 833.1
  TOP w10: 2166.05,1260.37 2166.05,1273.9 2192.19,1300.04 U2.B12@2192.19,1324.36 ; C12.1@2182.55,1225.1 2189.95,1225.1 2204.8,1210.25 2204.8,1151.05 2184.27,1130.52 ; 2188.95,1271.46 2217.78,1300.29 U2.B11@2217.78,1324.36
  TOP w12: U2.F5@2371.32,1426.72 2377.83,1426.72
  TOP w15: U2.D13@2166.6,1375.54 2202.19,1375.54 v1(2206.65,1380) ; U2.K13@2166.6,1529.08 2182.87,1529.08 v1(2185.75,1526.2) ; C12.1@2182.55,1225.1 2188.95,1231.5 2188.95,1271.46 ; U2.K5@2371.32,1529.08 2380.18,1529.08 v1(2396.5,1545.4) ; 2377.83,1426.72 v1(2388.75,1415.8)
  TOP w20: v1(1965,995.04) C91.2@1965,1034.87 ; 2151.55,1114.8 2151.55,1245.87 2166.05,1260.37 ; 2172,1109.5 2172,1118.25 2184.27,1130.52
  BOTTOM w20: 2112.65,1392.98 C53.1@2112.65,1414 ; 2112.65,1435.02 C53.1@2112.65,1414 ; C53.1@2132.07,1414 C53.1@2116.97,1414 C53.1@2112.65,1414 ; v1(2388.75,1415.8) 2400.06,1427.11 2410.75,1427.11 2433.85,1450.21 C51.1@2435.27,1450.21 ; v1(2396.5,1545.4) 2411,1559.9 2411,1568.5 2437.8,1595.3 C39.1@2442.75,1595.3
  other v1: 2118,970.5 2128.79,1030.54 2168.81,1031.38 2115.68,1081.18
AR_ANAMUX: P1.3 U2.C13 | length 2270.4
  TOP w4: U2.C13@2166.6,1349.95 2182.2,1349.95 v1(2185.95,1346.2)
  L3 w5: P1.3@31.27,1575.06 210.06,1396.27 385.08,1396.27 401.95,1379.4 2106.19,1379.4 2139.39,1346.2 v1(2185.95,1346.2)
AR_ANATEST1: R104.2 U2.P1 | length 3822.8
  TOP w4: R104.2@727.75,512.27 754,512.27 754,511.5 v1(764,511.5) ; U2.P1@2473.68,1631.44 2480.42,1631.44 2532,1683.02 2532,1706.66 2563.69,1738.34 2563.69,1827.19 v1(2578,1841.5)
  L3 w5: v1(764,511.5) 828.16,511.5 961.06,378.61 1597.42,378.61 1706.36,487.55 1799.89,487.55 1872.41,415.03 1872.41,305.11 1925.67,251.84 2032.92,251.84 2126.97,345.89 2126.97,735.23 2380.42,988.68 2552.76,988.68 2672,1107.92 2672,1639.42 2574.18,1737.25 2574.18,1805.3 2578,1809.13 v1(2578,1841.5)
AR_ANATEST2: R94.2 U2.P2 | length 3584.5
  TOP w4: R94.2@828.25,545.27 836.48,553.5 v1(864,553.5) ; U2.P2@2448.09,1631.44 2460.95,1644.3 2460.95,1661.98 2524.86,1725.89 2524.86,1738.36 v1(2540,1753.5)
  L3 w5: v1(864,553.5) 889.05,528.45 889.05,470.46 963.59,395.92 1202.19,395.92 1334.16,527.89 1786.02,527.89 1888.11,425.8 1888.11,315.63 1936.32,267.42 2030.95,267.42 2112.37,348.84 2112.37,743.08 2375.47,1006.18 2545.11,1006.18 2655.39,1116.46 2655.39,1638.11 v1(2540,1753.5)
AR_ANATEST3: R105.2 U2.P3 | length 3670
  TOP w4: R105.2@929.75,512.27 931.28,512.27 956.86,486.69 v1(956.86,440.79) ; U2.P3@2422.5,1631.44 2435.45,1644.39 2435.45,1666.95 2500,1731.5 2500,1812.5 v1(2531.5,1844)
  L3 w5: v1(956.86,440.79) 981.11,440.79 991.74,430.16 1068.11,430.16 1122.53,484.58 1200.35,484.58 1264.48,548.71 1792.67,548.71 1903.68,437.69 1903.68,323.69 1944.21,283.16 2028.16,283.16 2095.88,350.87 2095.88,787.34 2329.2,1020.66 2534.53,1020.66 2638.75,1124.88 2638.75,1491.26 2472.85,1657.16 2472.85,1692.35 2507.49,1726.99 2507.49,1819.99 v1(2531.5,1844)
AR_ANATEST4: R106.2 U2.R2 | length 3566.4
  TOP w4: R106.2@1030.25,512.27 1031.49,512.27 1049.72,494.04 1049.72,487.5 v1(1067.22,470) ; U2.R2@2448.09,1657.03 2448.09,1667.59 2511.41,1730.91 2511.41,1780.91 2552.3,1821.8 2552.3,1868.2 v1(2537,1883.5)
  L3 w5: v1(1067.22,470) 1094.81,497.59 1188.92,497.59 1261.58,570.25 1799.44,570.25 1917.36,452.33 1917.36,331.5 1950.06,298.8 2026.73,298.8 2079.84,351.91 2079.84,796.88 2325.09,1042.12 2528.62,1042.12 2620.05,1133.55 2620.05,1490.89 2459.96,1650.98 2459.96,1699.98 2492.58,1732.6 2492.58,1839.08 v1(2537,1883.5)
AR_BSS_LOGGER: R31.1 R135.1 U2.R4 | length 3430.8
  TOP w4: U2.R4@2396.91,1657.03 2396.91,1664.41 2465.49,1732.99 2465.49,1844.4 v1(2451.13,1858.76)
  TOP w5: R31.1@1182.65,2139.15 1185.37,2141.87 v1(1206.66,2141.87)
  L3 w5: v1(442,2020.5) 470.43,2020.5 486.56,2036.63 651.36,2036.63 736.99,2122.26 942.38,2122.26 949.03,2128.9 1016.89,2128.9 1023.53,2122.26 1099.51,2122.26 1119.12,2141.87 v1(1206.66,2141.87) 1269.96,2141.87 1300.19,2172.1 1326.8,2172.1 1423.44,2075.45 1669.77,2075.45 1776.94,2182.62 2107.47,2182.62 2282.52,2007.58 2282.52,1944.35 2314.39,1912.48 2397.42,1912.48 v1(2451.13,1858.76)
  BOTTOM w4: R135.1@121.79,1366.19 85,1402.98 85,1696.18 184.32,1795.5 217,1795.5 v1(442,2020.5)
AR_CS1: U2.R7 U13.10 | length 2799.2
  TOP w4: v1(1067.5,1143.73) 1083.98,1160.21 U13.10@1083.98,1175.71 ; U2.R7@2320.14,1657.03 2315.55,1661.63 2315.55,1671.77 2310.55,1676.77 2310.55,1796.15 2346.47,1832.07 2346.47,1866.84 2336.3,1877.01 2336.3,1909.5 v1(2362.38,1935.58)
  L3 w4: v1(1067.5,1143.73) 1051.19,1143.73 1045.05,1137.59 1011.49,1137.59 985.8,1163.28 985.8,1201.38 1014.57,1230.15 1139.06,1230.15 1245.47,1336.55 1980.09,1336.55 2029.86,1286.79 2416.28,1286.79 2523.8,1394.31 2523.8,1571.37 2447.53,1647.63 2447.53,1707.3 2475.65,1735.41 2475.65,1863.92 2410.04,1929.53 2387.15,1929.53 2381.1,1935.58 v1(2362.38,1935.58)
AR_GPIO_0: R164.1 R177.2 U2.N4 | length 3718.2
  TOP w4: v1(1092.13,416.62) 1092.13,542.93 1118.2,569 1134.25,569 1150.96,585.71 1150.96,594.81 1209.5,653.36 R177.2@1209.5,656.88 ; v1(2392.34,1587.4) 2396.91,1591.97 U2.N4@2396.91,1605.85
  L3 w5: v1(1358,220) 1413,220 1487.1,145.9 1797.11,145.9 1883.52,232.31 2032.28,232.31 2142.6,342.63 2142.6,727.18 2386.2,970.78 2560.31,970.78 2689.9,1100.38 2689.9,1650.98 v1(2595.65,1745.24)
  L4 w6: v1(2392.34,1587.4) 2394,1589.06 2394,1613.96 2499.54,1719.5 2569.91,1719.5 v1(2595.65,1745.24)
  BOTTOM w4: v1(1092.13,416.62) 1139.72,416.62 1195.4,360.94 1238.59,360.94 1266.44,333.09 1266.44,284.55 1302.99,248 1330,248 v1(1358,220) 1370,208 1370,175.98 R164.1@1352.75,158.73
AR_GPIO_1: R9.2 R72.2 U2.N7 | length 3760.8
  TOP w4: R72.2@192.5,1474.24 204.83,1486.57 v1(204.83,1515.16) ; R9.2@829.75,2228.73 853.51,2228.73 v1(868.03,2243.25) ; U2.N7@2320.14,1605.85 2338.45,1587.54 v1(2338.45,1585.1)
  L3 w4: v1(204.83,1515.16) 241.82,1552.15 241.82,1700.01 263.32,1721.51 263.32,1878.18 v1(239,1902.5)
  L3 w5: v1(868.03,2243.25) 868.03,2265.26 945.86,2343.08 2086.2,2343.08 2466.13,1963.16 2482.34,1963.16 v1(2503,1942.5)
  L4 w6: v1(2338.45,1585.1) 2503,1749.65 v1(2503,1942.5)
  BOTTOM w4: v1(239,1902.5) 393,2056.5 393,2216.5 491.72,2315.22 743.28,2315.22 772,2286.5 838,2286.5 868.03,2256.47 v1(868.03,2243.25) 864.75,2243.25 v1@861,2239.5
AR_GPIO_2: R8.2 R110.2 R116.1 U2.N13 | length 4502.3
  TOP w4: R110.2@-11.18,459.77 -11.12,459.71 v1(-11.12,373.5) ; R8.2@1329.55,2229.73 1369,2190.28 v1(1369,2172.5) ; v1(1499.21,1871.03) 1547.26,1871.03 1565.47,1889.24 1677.58,1889.24 1697.56,1869.26 1738.21,1869.26 1763.01,1844.46 1798.79,1844.46 1965.71,1677.54 2027.96,1677.54 2087,1618.5 2146.1,1618.5 2158.75,1605.85 U2.N13@2166.6,1605.85
  L3 w5: v1(62,1915.5) 79.02,1932.52 276.98,1932.52 355.12,1854.38 490.88,1854.38 581.05,1944.55 1081.95,1944.55 1189.89,1836.61 1464.8,1836.61 v1(1499.21,1871.03)
  BOTTOM w4: v1(-11.12,373.5) -68.67,431.05 -68.67,1787.83 59,1915.5 v1(62,1915.5) ; v1(1369,2172.5) 1499.21,2042.29 v1(1499.21,1871.03)
AR_HOSTINTR1: R10.2 R13.2 R64.2 U2.P6 | length 2434.7
  TOP w4: R64.2@1026.61,1598.73 1035.23,1598.73 1043,1606.5 1043,1692.5 v1(1046,1695.5) ; R13.2@1198.4,2214.36 1224.88,2214.36 R10.2@1239.25,2228.73 1255.34,2212.64 1268.02,2212.64 1314.1,2166.56 v1(1314.1,2150.9) ; U2.P6@2345.73,1631.44 2332.91,1644.26 2332.91,1669.44 2318.55,1683.8 2318.55,1792.83 2358.19,1832.48 v1(2358.19,1892.76)
  L3 w5: v1(1314.1,2150.9) 1409.62,2055.38 1669.06,2055.38 1780.66,2166.98 2100.41,2166.98 2252.01,2015.37 2252.01,1958.79 2318.05,1892.76 v1(2358.19,1892.76)
  BOTTOM w4: v1(1046,1695.5) 1046,1792.5 1172.2,1918.7 1172.2,2059.74 1225.75,2113.29 1276.49,2113.29 v1(1314.1,2150.9)
AR_LVDS_VALID_N: R60.2 U2.N14 | length 1930.5
  TOP w4: 2108.58,1592.91 2128.07,1592.91 U2.N14@2141.01,1605.85
  TOP w5.2: R60.2@865.55,1598.73 865.55,1487.96 878.58,1474.93 1181.43,1474.93 1233.11,1526.61 1233.11,1704.06 1247.51,1718.46 1283.9,1718.46 1299.44,1702.92 1299.44,1600.59 1313.11,1586.92 1370.46,1586.92 1408.08,1549.3 1731.83,1549.3 1793.84,1611.31 1842.55,1611.31 1873.93,1642.69 1873.93,1705.01 1880.02,1711.1 1888.64,1711.1 1894.73,1705.01 1894.73,1650.87 1914.39,1631.21 1970.21,1631.21 1987.71,1648.71 2016.79,1648.71 2072.59,1592.91 2108.58,1592.91
AR_LVDS_VALID_P: R61.2 U2.N15 | length 1930.8
  TOP w5.2: R61.2@897.75,1598.73 890,1590.98 890,1580.5 895,1575.5 906.8,1575.5 912,1570.3 912,1560.7 906.8,1555.5 885,1555.5 875.75,1546.25 875.75,1492.19 882.81,1485.13 1177.2,1485.13 1222.91,1530.84 1222.91,1708.28 1243.29,1728.66 1288.12,1728.66 1309.64,1707.14 1309.64,1604.82 1317.34,1597.12 1374.69,1597.12 1412.31,1559.5 1727.61,1559.5 1789.61,1621.51 1838.33,1621.51 1863.73,1646.91 1863.73,1709.24 1875.79,1721.3 1892.87,1721.3 1904.93,1709.24 1904.93,1655.1 1918.62,1641.41 1965.98,1641.41 1983.48,1658.91 2021.02,1658.91 2076.82,1603.11 2108.58,1603.11 2111.32,1605.85 U2.N15@2115.42,1605.85
AR_LVDSCSI0_N: R48.2 U2.G14 | length 1930.5
  TOP w5.2: R48.2@475.61,1598.73 484,1590.34 484,1465.08 655.05,1294.04 1402.98,1294.04 1447.73,1338.79 1830.98,1338.79 1930.51,1438.32 2127.02,1438.32 U2.G14@2141.01,1452.31
AR_LVDSCSI0_P: R49.2 U2.G15 | length 1930.6
  TOP w5.2: R49.2@508.25,1598.73 500.58,1591.06 500.58,1583.7 505.78,1578.5 521.8,1578.5 527,1573.3 527,1564.7 521.8,1559.5 499.4,1559.5 494.2,1554.3 494.2,1469.31 659.27,1304.24 1398.75,1304.24 1443.5,1348.99 1826.76,1348.99 1926.29,1448.52 2099.22,1448.52 2103.01,1452.31 U2.G15@2115.42,1452.31
AR_LVDSCSI1_N: R50.2 U2.H14 | length 1931
  TOP w4: 2108.32,1464.96 2128.07,1464.96 U2.H14@2141.01,1477.9
  TOP w5.2: R50.2@540.75,1598.73 541.77,1598.73 549,1591.5 549,1446.77 562.37,1433.4 578.91,1433.4 596.01,1450.5 604.01,1450.5 611.06,1443.45 611.06,1436.09 593.64,1418.67 593.64,1402.87 679.21,1317.3 1377.61,1317.3 1426.4,1366.09 1821.53,1366.09 1920.74,1465.3 2107.98,1465.3 2108.32,1464.96
AR_LVDSCSI1_P: R51.2 U2.H15 | length 1931
  TOP w5.2: R51.2@573.25,1598.73 566,1591.48 566,1583.5 570,1579.5 586.43,1579.5 592.87,1573.06 592.87,1565.7 587.67,1560.5 565,1560.5 559.2,1554.7 559.2,1450.99 566.59,1443.6 574.68,1443.6 591.78,1460.7 608.24,1460.7 621.26,1447.68 621.26,1431.86 603.84,1414.44 603.84,1407.1 683.44,1327.5 1373.39,1327.5 1422.17,1376.28 1817.3,1376.28 1916.52,1475.5 2113.02,1475.5 U2.H15@2115.42,1477.9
